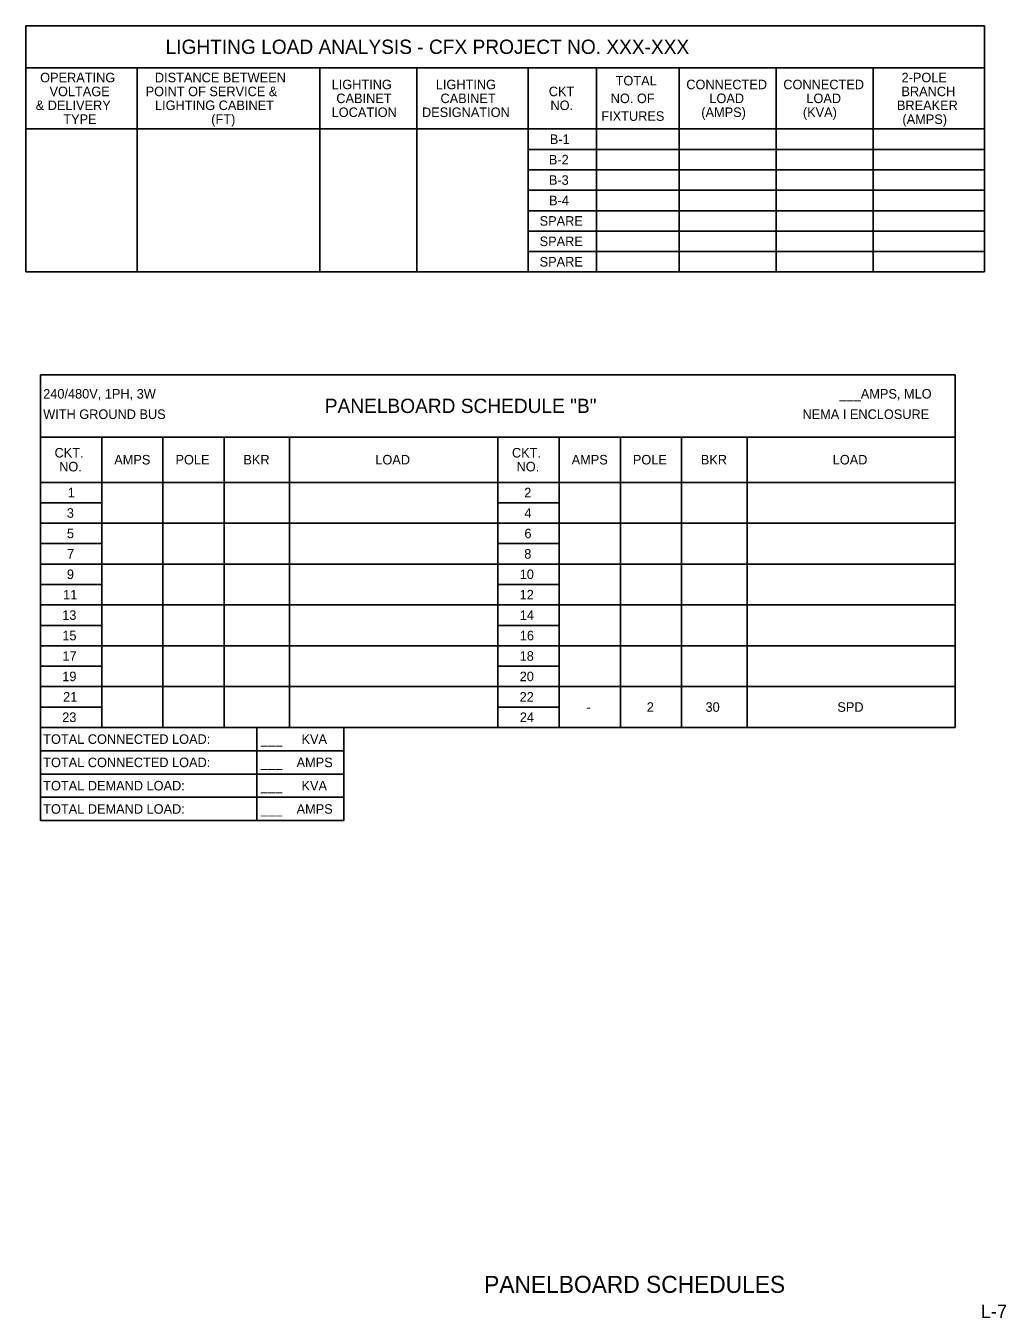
# Model space of a CAD drawing. Extents: x 856079 to 2148480, y 462635 to 2147771.
# Drawn here: x 2148473.14 to 2148480.34, y 2147761.82 to 2147771.31 of the extents above; entities that cross this region are included whole.
import ezdxf

# ---------------------------------------------------------------- set-up
doc = ezdxf.new("R2010")
doc.units = 0
for name, color, linetype in [('FLMap5', 7, 'Continuous'), ('NonPlottingEle_dp', 7, 'Continuous'), ('SignPanel', 7, 'Continuous'), ('SumBoxBorder_dp', 7, 'Continuous'), ('SumBoxLines_dp', 7, 'Continuous')]:
    doc.layers.add(name, color=color, linetype=linetype)

msp = doc.modelspace()

# ---------------------------------------------------------------- linework, layer by layer
at = {"layer": 'SumBoxBorder_dp'}
for p, q in [((2148473.1374, 2147771.3129), (2148480.1799, 2147771.3129)), ((2148473.1374, 2147771.3129), (2148473.1374, 2147769.5054)), ((2148480.1799, 2147771.3129), (2148480.1799, 2147769.5054)), ((2148473.1374, 2147771.0054), (2148480.1799, 2147771.0054)), ((2148473.1374, 2147771.0054), (2148480.1799, 2147771.0054)), ((2148473.1374, 2147769.5054), (2148480.1799, 2147769.5054)), ((2148473.2449, 2147768.7509), (2148479.9649, 2147768.7509)), ((2148473.2449, 2147768.7509), (2148473.2449, 2147765.4764)), ((2148479.9649, 2147768.7509), (2148479.9649, 2147766.1604)), ((2148473.2449, 2147768.2934), (2148479.9649, 2147768.2934)), ((2148473.2449, 2147768.2934), (2148479.9649, 2147768.2934)), ((2148473.2449, 2147766.1604), (2148479.9649, 2147766.1604)), ((2148473.2449, 2147766.1604), (2148479.9649, 2147766.1604)), ((2148474.8349, 2147766.1604), (2148474.8349, 2147765.4764)), ((2148474.8349, 2147766.1604), (2148474.8349, 2147765.4764)), ((2148475.4724, 2147766.1604), (2148475.4724, 2147765.4764)), ((2148475.4724, 2147766.1604), (2148475.4724, 2147765.4764)), ((2148473.2449, 2147765.9894), (2148475.4724, 2147765.9894)), ((2148473.2449, 2147765.9894), (2148475.4724, 2147765.9894)), ((2148473.2449, 2147765.8184), (2148475.4724, 2147765.8184)), ((2148473.2449, 2147765.8184), (2148475.4724, 2147765.8184)), ((2148473.2449, 2147765.6474), (2148475.4724, 2147765.6474)), ((2148473.2449, 2147765.6474), (2148475.4724, 2147765.6474)), ((2148473.2449, 2147765.4764), (2148475.4724, 2147765.4764))]:
    msp.add_line(p, q, dxfattribs=at)
at = {"layer": 'SumBoxLines_dp'}
for p, q in [((2148473.9549, 2147771.0054), (2148473.9549, 2147769.5054)), ((2148473.9549, 2147771.0054), (2148473.9549, 2147769.5054)), ((2148475.2974, 2147771.0054), (2148475.2974, 2147769.5054)), ((2148475.2974, 2147771.0054), (2148475.2974, 2147769.5054)), ((2148476.0099, 2147771.0054), (2148476.0099, 2147769.5054)), ((2148476.0099, 2147771.0054), (2148476.0099, 2147769.5054)), ((2148476.8274, 2147771.0054), (2148476.8274, 2147769.5054)), ((2148476.8274, 2147771.0054), (2148476.8274, 2147769.5054)), ((2148477.3299, 2147771.0054), (2148477.3299, 2147769.5054)), ((2148477.3299, 2147771.0054), (2148477.3299, 2147769.5054)), ((2148477.9374, 2147771.0054), (2148477.9374, 2147769.5054)), ((2148477.9374, 2147771.0054), (2148477.9374, 2147769.5054)), ((2148478.6499, 2147771.0054), (2148478.6499, 2147769.5054)), ((2148478.6499, 2147771.0054), (2148478.6499, 2147769.5054)), ((2148479.3624, 2147771.0054), (2148479.3624, 2147769.5054)), ((2148479.3624, 2147771.0054), (2148479.3624, 2147769.5054)), ((2148473.1374, 2147770.5554), (2148480.1799, 2147770.5554)), ((2148473.1374, 2147770.5554), (2148480.1799, 2147770.5554)), ((2148476.8274, 2147770.4054), (2148480.1799, 2147770.4054)), ((2148476.8274, 2147770.4054), (2148480.1799, 2147770.4054)), ((2148476.8274, 2147770.2554), (2148480.1799, 2147770.2554)), ((2148476.8274, 2147770.2554), (2148480.1799, 2147770.2554)), ((2148476.8274, 2147770.1054), (2148480.1799, 2147770.1054)), ((2148476.8274, 2147770.1054), (2148480.1799, 2147770.1054)), ((2148476.8274, 2147769.9554), (2148480.1799, 2147769.9554)), ((2148476.8274, 2147769.9554), (2148480.1799, 2147769.9554)), ((2148476.8274, 2147769.8054), (2148480.1799, 2147769.8054)), ((2148476.8274, 2147769.8054), (2148480.1799, 2147769.8054)), ((2148476.8274, 2147769.6554), (2148480.1799, 2147769.6554)), ((2148476.8274, 2147769.6554), (2148480.1799, 2147769.6554)), ((2148473.6949, 2147768.2934), (2148473.6949, 2147766.1604)), ((2148473.6949, 2147768.2934), (2148473.6949, 2147766.1604)), ((2148474.1449, 2147768.2934), (2148474.1449, 2147766.1604)), ((2148474.1449, 2147768.2934), (2148474.1449, 2147766.1604)), ((2148474.5949, 2147768.2934), (2148474.5949, 2147766.1604)), ((2148474.5949, 2147768.2934), (2148474.5949, 2147766.1604)), ((2148475.0749, 2147768.2934), (2148475.0749, 2147766.1604)), ((2148475.0749, 2147768.2934), (2148475.0749, 2147766.1604)), ((2148476.6049, 2147768.2934), (2148476.6049, 2147766.1604)), ((2148477.0549, 2147768.2934), (2148477.0549, 2147766.1604)), ((2148477.0549, 2147768.2934), (2148477.0549, 2147766.1604)), ((2148477.5049, 2147768.2934), (2148477.5049, 2147766.1604)), ((2148477.5049, 2147768.2934), (2148477.5049, 2147766.1604)), ((2148477.9549, 2147768.2934), (2148477.9549, 2147766.1604)), ((2148477.9549, 2147768.2934), (2148477.9549, 2147766.1604)), ((2148478.4349, 2147768.2934), (2148478.4349, 2147766.1604)), ((2148478.4349, 2147768.2934), (2148478.4349, 2147766.1604)), ((2148473.2449, 2147767.9604), (2148479.9649, 2147767.9604)), ((2148473.2449, 2147767.9604), (2148479.9649, 2147767.9604)), ((2148476.6049, 2147767.9604), (2148476.6049, 2147766.1604)), ((2148473.2449, 2147767.8104), (2148473.6949, 2147767.8104)), ((2148476.6049, 2147767.8104), (2148477.0549, 2147767.8104)), ((2148473.2449, 2147767.6604), (2148479.9649, 2147767.6604)), ((2148473.2449, 2147767.6604), (2148479.9649, 2147767.6604)), ((2148473.2449, 2147767.5104), (2148473.6949, 2147767.5104)), ((2148473.2449, 2147767.5104), (2148473.6949, 2147767.5104)), ((2148476.6049, 2147767.5104), (2148477.0549, 2147767.5104)), ((2148476.6049, 2147767.5104), (2148477.0549, 2147767.5104)), ((2148473.2449, 2147767.3604), (2148479.9649, 2147767.3604)), ((2148473.6949, 2147767.3604), (2148476.6049, 2147767.3604)), ((2148477.0549, 2147767.3604), (2148479.9649, 2147767.3604)), ((2148473.2449, 2147767.2104), (2148473.6949, 2147767.2104)), ((2148473.2449, 2147767.2104), (2148473.6949, 2147767.2104)), ((2148476.6049, 2147767.2104), (2148477.0549, 2147767.2104)), ((2148476.6049, 2147767.2104), (2148477.0549, 2147767.2104)), ((2148473.2449, 2147767.0604), (2148479.9649, 2147767.0604)), ((2148473.2449, 2147767.0604), (2148479.9649, 2147767.0604)), ((2148473.2449, 2147766.9104), (2148473.6949, 2147766.9104)), ((2148476.6049, 2147766.9104), (2148477.0549, 2147766.9104)), ((2148473.2449, 2147766.7604), (2148479.9649, 2147766.7604)), ((2148473.2449, 2147766.7604), (2148479.9649, 2147766.7604)), ((2148473.2449, 2147766.6104), (2148473.6949, 2147766.6104)), ((2148473.2449, 2147766.6104), (2148473.6949, 2147766.6104)), ((2148476.6049, 2147766.6104), (2148477.0549, 2147766.6104)), ((2148476.6049, 2147766.6104), (2148477.0549, 2147766.6104)), ((2148473.2449, 2147766.4604), (2148479.9649, 2147766.4604)), ((2148473.6949, 2147766.4604), (2148476.6049, 2147766.4604)), ((2148477.0549, 2147766.4604), (2148479.9649, 2147766.4604)), ((2148473.2449, 2147766.3104), (2148473.6949, 2147766.3104)), ((2148473.2449, 2147766.3104), (2148473.6949, 2147766.3104)), ((2148476.6049, 2147766.3104), (2148477.0549, 2147766.3104)), ((2148476.6049, 2147766.3104), (2148477.0549, 2147766.3104))]:
    msp.add_line(p, q, dxfattribs=at)

# ---------------------------------------------------------------- texts
at = {"layer": 'FLMap5'}
for s, height, p in [('LIGHTING LOAD ANALYSIS - CFX PROJECT NO. XXX-XXX', 0.105, (2148474.1638, 2147771.1067)), ('OPERATING', 0.07, (2148473.2425, 2147770.8984)), ('DISTANCE BETWEEN', 0.07, (2148474.0854, 2147770.8984)), ('LIGHTING', 0.07, (2148475.3839, 2147770.8474)), ('LIGHTING', 0.07, (2148476.1489, 2147770.8474)), ('TOTAL', 0.07, (2148477.47, 2147770.8754)), ('CONNECTED', 0.07, (2148477.989, 2147770.8474)), ('CONNECTED', 0.07, (2148478.7015, 2147770.8474)), ('2-POLE', 0.07, (2148479.5701, 2147770.8984)), ('VOLTAGE', 0.07, (2148473.3112, 2147770.7964)), ('POINT OF SERVICE &', 0.07, (2148474.0176, 2147770.7964)), ('CABINET', 0.07, (2148475.4183, 2147770.7454)), ('CABINET', 0.07, (2148476.1833, 2147770.7454)), ('CKT', 0.07, (2148476.9788, 2147770.7964)), ('NO. OF', 0.07, (2148477.4336, 2147770.7454)), ('LOAD', 0.07, (2148478.1584, 2147770.7454)), ('LOAD', 0.07, (2148478.8709, 2147770.7454)), ('BRANCH', 0.07, (2148479.5692, 2147770.7964)), ('& DELIVERY', 0.07, (2148473.2097, 2147770.6944)), ('LIGHTING CABINET', 0.07, (2148474.0859, 2147770.6944)), ('NO.', 0.07, (2148476.991, 2147770.6944)), ('(AMPS)', 0.07, (2148478.099, 2147770.6434)), ('(KVA)', 0.07, (2148478.8454, 2147770.6434)), ('BREAKER', 0.07, (2148479.5362, 2147770.6944)), ('TYPE', 0.07, (2148473.4128, 2147770.5924)), ('(FT)', 0.07, (2148474.4993, 2147770.5924)), ('LOCATION', 0.07, (2148475.3839, 2147770.6434)), ('DESIGNATION', 0.07, (2148476.0473, 2147770.6434)), ('FIXTURES', 0.07, (2148477.365, 2147770.6154)), ('(AMPS)', 0.07, (2148479.5765, 2147770.5924)), ('B-1', 0.07, (2148476.9862, 2147770.4454)), ('B-2', 0.07, (2148476.9795, 2147770.2954)), ('B-3', 0.07, (2148476.9794, 2147770.1454)), ('B-4', 0.07, (2148476.9808, 2147769.9954)), ('SPARE', 0.07, (2148476.9115, 2147769.8454)), ('SPARE', 0.07, (2148476.9115, 2147769.6954)), ('SPARE', 0.07, (2148476.9115, 2147769.5454)), ('240/480V, 1PH, 3W', 0.07, (2148473.2649, 2147768.5759)), ('___AMPS, MLO', 0.07, (2148479.1146, 2147768.5759)), ('PANELBOARD SCHEDULE "B"', 0.105, (2148475.3334, 2147768.4697)), ('WITH GROUND BUS', 0.07, (2148473.2649, 2147768.4259)), ('NEMA I ENCLOSURE', 0.07, (2148478.8422, 2147768.4259)), ('CKT.', 0.07, (2148473.3483, 2147768.1429)), ('AMPS', 0.07, (2148473.7868, 2147768.0919)), ('POLE', 0.07, (2148474.2366, 2147768.0919)), ('BKR', 0.07, (2148474.7354, 2147768.0919)), ('LOAD', 0.07, (2148475.7046, 2147768.0919)), ('CKT.', 0.07, (2148476.7083, 2147768.1429)), ('AMPS', 0.07, (2148477.1468, 2147768.0919)), ('POLE', 0.07, (2148477.5966, 2147768.0919)), ('BKR', 0.07, (2148478.0954, 2147768.0919)), ('LOAD', 0.07, (2148479.0646, 2147768.0919)), ('NO.', 0.07, (2148473.3822, 2147768.0409)), ('NO.', 0.07, (2148476.7422, 2147768.0409)), ('1', 0.07, (2148473.4452, 2147767.8504)), ('2', 0.07, (2148476.7985, 2147767.8504)), ('3', 0.07, (2148473.4384, 2147767.7004)), ('4', 0.07, (2148476.7998, 2147767.7004)), ('5', 0.07, (2148473.4393, 2147767.5504)), ('6', 0.07, (2148476.7999, 2147767.5504)), ('7', 0.07, (2148473.4405, 2147767.4004)), ('8', 0.07, (2148476.7987, 2147767.4004)), ('9', 0.07, (2148473.4389, 2147767.2504)), ('10', 0.07, (2148476.7652, 2147767.2504)), ('11', 0.07, (2148473.4113, 2147767.1004)), ('12', 0.07, (2148476.7646, 2147767.1004)), ('13', 0.07, (2148473.4046, 2147766.9504)), ('14', 0.07, (2148476.766, 2147766.9504)), ('15', 0.07, (2148473.4055, 2147766.8004)), ('16', 0.07, (2148476.766, 2147766.8004)), ('17', 0.07, (2148473.4066, 2147766.6504)), ('18', 0.07, (2148476.7648, 2147766.6504)), ('19', 0.07, (2148473.405, 2147766.5004)), ('20', 0.07, (2148476.7652, 2147766.5004)), ('21', 0.07, (2148473.4113, 2147766.3504)), ('22', 0.07, (2148476.7646, 2147766.3504)), ('23', 0.07, (2148473.4046, 2147766.2004)), ('24', 0.07, (2148476.766, 2147766.2004)), ('-', 0.07, (2148477.2563, 2147766.2754)), ('2', 0.07, (2148477.6985, 2147766.2754)), ('30', 0.07, (2148478.1302, 2147766.2754)), ('SPD', 0.07, (2148479.0985, 2147766.2754)), ('TOTAL CONNECTED LOAD:', 0.07, (2148473.2649, 2147766.0399)), ('KVA', 0.07, (2148475.1623, 2147766.0399)), ('___', 0.07, (2148474.8639, 2147766.0399)), ('TOTAL CONNECTED LOAD:', 0.07, (2148473.2649, 2147765.8689)), ('AMPS', 0.07, (2148475.1263, 2147765.8689)), ('___', 0.07, (2148474.8639, 2147765.8689)), ('TOTAL DEMAND LOAD:', 0.07, (2148473.2649, 2147765.6979)), ('KVA', 0.07, (2148475.1623, 2147765.6979)), ('TOTAL DEMAND LOAD:', 0.07, (2148473.2649, 2147765.5269)), ('___', 0.07, (2148474.8639, 2147765.6979)), ('AMPS', 0.07, (2148475.1263, 2147765.5269)), ('___', 0.07, (2148474.8639, 2147765.5269))]:
    msp.add_text(s, height=height, dxfattribs=at).set_placement(p)
at = {"layer": 'NonPlottingEle_dp'}
msp.add_text('L-7', height=0.1, dxfattribs=at).set_placement((2148480.152, 2147761.8225))
at = {"layer": 'SignPanel'}
msp.add_text('     PANELBOARD SCHEDULES      ', height=0.125, dxfattribs=at).set_placement((2148476.272, 2147762.0082))

doc.saveas('drawing.dxf')
